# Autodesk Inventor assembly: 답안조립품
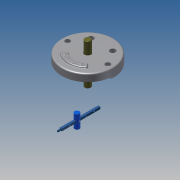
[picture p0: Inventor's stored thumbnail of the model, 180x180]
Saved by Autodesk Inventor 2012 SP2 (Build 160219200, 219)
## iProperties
Created: 2015-04
Part Number: 답안조립품
Document SubType Name: Assembly
Designer: Administrator
Author: Administrator
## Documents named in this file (8)
- C:\Users\Administrator\Desktop\450406V1005\답안조립품.iam
- C:\Users\Administrator\Desktop\450406V1005\1-본체.ipt
- C:\Users\Administrator\Desktop\450406V1005\축.ipt
- C:\Users\Administrator\Desktop\450406V1005\베어링62_22.ipt
- C:\Users\Administrator\Desktop\450406V1005\멈춤링.ipt
- C:\Users\Administrator\Desktop\450406V1005\슬라이더.ipt
- C:\Users\Administrator\Desktop\450406V1005\슬라이더2.ipt
- C:\Users\Administrator\Desktop\450406V1005\평행핀.ipt
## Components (1 placed, 1 different names)
1. 1-본체:1
